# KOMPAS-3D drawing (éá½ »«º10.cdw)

Referenced files: ВалМой01.cdw
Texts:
  Вал тихоходный
  OlegKR
  Noncommercial version
  Ra0.8
  Ra1.6
  Ra3.2
  Ra6.3
  260...285 НВ.
  Неуказанные предельные размеры валов -t 2 , остальных  t 2 /2, по ГОСТ  30893.1-2002.
  Сталь 45  ГОСТ 1050-88
Dimensions and other numbers on the sheet: 36; 40; 45; 53; 70; 57; 54; 2,5; 224; 2; 2 фаски; 2 канавки; 0,02; 0,025; 0,03; 3,2; 3; 0,25; 1; 34; 14; 10; 26; 1:1; 2,3; 0; 4; 5; 6; 7; 8; 9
